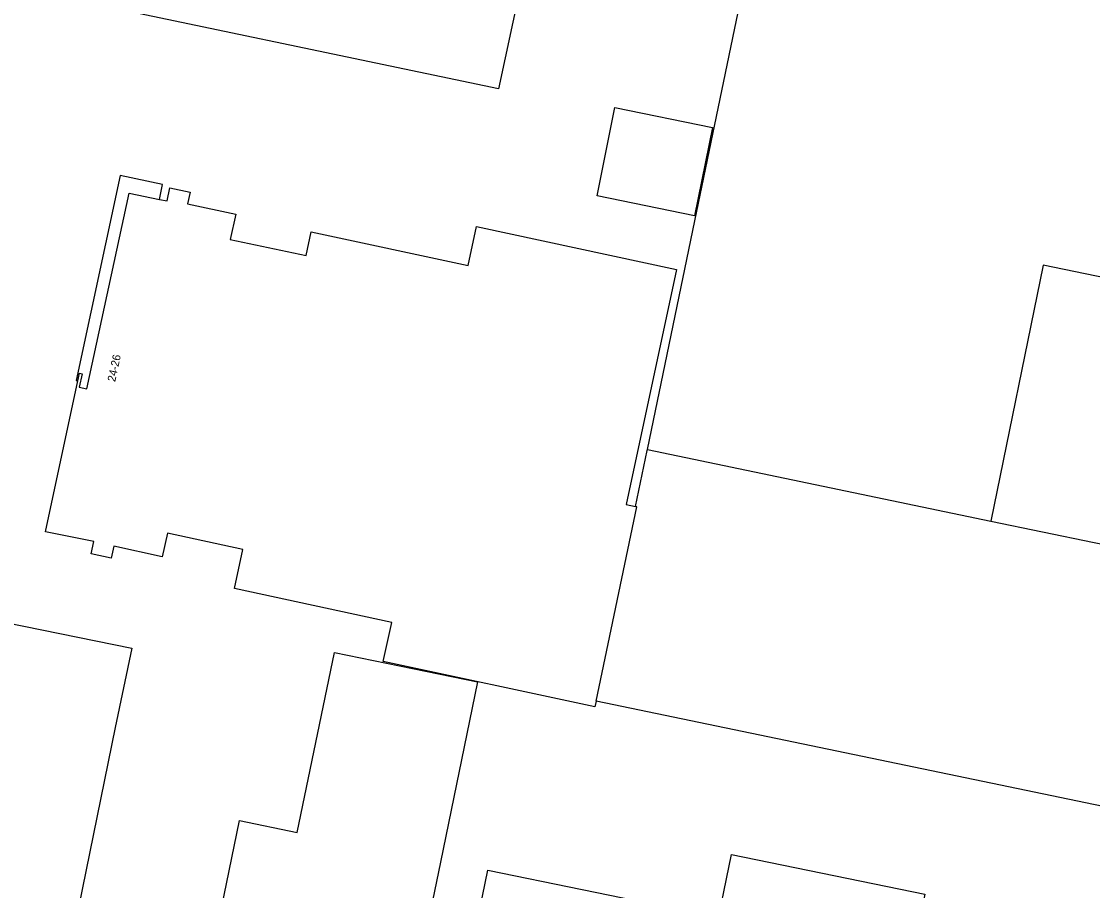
# Model space of a CAD drawing. Extents: x 157692 to 159670, y 381454 to 383289.
# Drawn here: x 158232.1 to 158365.6, y 382592.2 to 382700.6 of the extents above; entities that cross this region are included whole.
import ezdxf

# ---------------------------------------------------------------- set-up
doc = ezdxf.new("R2010")
doc.units = 0
for name, color, linetype in [('IMGEO_Pand', 7, 'Continuous'), ('IMGEO_Pand_nummerreeks', 7, 'Continuous'), ('IMGEO_Pand_overbouw', 7, 'Continuous')]:
    doc.layers.add(name, color=color, linetype=linetype)

msp = doc.modelspace()

# ---------------------------------------------------------------- linework, layer by layer
at = {"layer": 'IMGEO_Pand'}
for points in [[(158233.14, 382704.51), (158233.31, 382705.3), (158239.85, 382736.2), (158235.29, 382737.16), (158236.84, 382744.62), (158271.08, 382737.39), (158270.37, 382733.89), (158299.12, 382727.79), (158296.85, 382717.09), (158302.18, 382715.96), (158299.49, 382703.32), (158294.17, 382704.46), (158291.57, 382692.24), (158233.14, 382704.51)], [(158310.13, 382647.23), (158316.03, 382675.76), (158321.89, 382704.06), (158322.9, 382708.96), (158328.21, 382707.89), (158330.83, 382720.57), (158358, 382715), (158357.94, 382714.69), (158357.59, 382714.75), (158357.35, 382713.59), (158362.29, 382712.55), (158362.54, 382713.72), (158362.15, 382713.8), (158362.22, 382714.11), (158389.37, 382708.39), (158386.74, 382695.68), (158392.04, 382694.57), (158391.03, 382689.67), (158385.9, 382664.78), (158359.48, 382670.22), (158352.94, 382638.28)], [(158303.85, 382678.9), (158306.06, 382689.91), (158318.27, 382687.39), (158315.99, 382676.39), (158303.85, 382678.9)], [(158303.74, 382615.84), (158303.59, 382615.12), (158277.18, 382620.79), (158278.25, 382625.65), (158258.64, 382629.89), (158259.7, 382634.76), (158250.27, 382636.79), (158249.62, 382633.84), (158243.58, 382635.15), (158243.26, 382633.67), (158240.77, 382634.22), (158241.11, 382635.73), (158235.07, 382636.97), (158239.11, 382655.79), (158239.32, 382656.76), (158239.63, 382656.69), (158239.27, 382655.01), (158240.23, 382654.8), (158245.49, 382679.23), (158249.27, 382678.44), (158250.23, 382678.24), (158250.59, 382679.9), (158253.1, 382679.35), (158252.77, 382677.89), (158258.8, 382676.59), (158258.12, 382673.44), (158267.56, 382671.42), (158268.19, 382674.38), (158287.78, 382670.18), (158288.83, 382675.04), (158313.78, 382669.69), (158307.48, 382640.35), (158308.65, 382640.1)], [(158308.65, 382640.1), (158310.11, 382647.12), (158310.13, 382647.23)], [(158310.13, 382647.23), (158352.94, 382638.28)], [(158303.74, 382615.84), (158308.82, 382640.07), (158308.65, 382640.1)], [(158352.94, 382638.28), (158391.62, 382630.32), (158385.16, 382598.9), (158303.74, 382615.84)], [(158206.93, 382583.15), (158214.19, 382618.55), (158219.17, 382617.54), (158219.47, 382619.02), (158220.15, 382622.37), (158227.41, 382620.9), (158227.57, 382621.68), (158227.77, 382622.63), (158227.35, 382622.71), (158227.43, 382623.1), (158227.84, 382623.01), (158228.44, 382625.97), (158229.8, 382625.7), (158229.88, 382626.12), (158230.22, 382626.05), (158230.14, 382625.63), (158245.82, 382622.45), (158243.76, 382612.55), (158236.47, 382576.8)], [(158278.52, 382567.58), (158277.52, 382562.68), (158271.57, 382563.89), (158265.48, 382565.14), (158252.48, 382567.79), (158252.71, 382568.92), (158249.67, 382569.54), (158249.44, 382568.41), (158249.1, 382568.48), (158251.4, 382579.74), (158254.78, 382579.05), (158259.25, 382600.93), (158266.46, 382599.44), (158271.1, 382621.91), (158288.94, 382618.22), (158284.32, 382595.75), (158278.52, 382567.58)], [(158344.72, 382591.73), (158338.21, 382560.07), (158337.21, 382555.17), (158335.3, 382555.59), (158331.44, 382545.45), (158315.35, 382551.58), (158315.45, 382551.88), (158317.62, 382551.14), (158319.14, 382555.26), (158318.49, 382555.38), (158318.99, 382557.93), (158320.06, 382557.73), (158320.39, 382558.62), (158318.99, 382558.9), (158319.99, 382563.8), (158321.08, 382569.15), (158315.21, 382570.33), (158316.21, 382575.23), (158320.62, 382596.68), (158344.72, 382591.73)], [(158307.71, 382560.55), (158306.71, 382555.65), (158295.16, 382558.04), (158292.52, 382558.58), (158291.43, 382561.73), (158289.69, 382562.23), (158293.14, 382578.91), (158287.24, 382580.09), (158288.24, 382584.99), (158290.24, 382594.75), (158313.75, 382589.93), (158307.71, 382560.55)]]:
    msp.add_lwpolyline(points, dxfattribs=at)
at = {"layer": 'IMGEO_Pand_overbouw'}
msp.add_lwpolyline([(158249.27, 382678.44), (158249.66, 382680.3), (158244.38, 382681.44), (158238.88, 382655.83), (158239.11, 382655.79), (158239.32, 382656.76), (158239.63, 382656.69), (158239.27, 382655.01), (158240.23, 382654.8), (158245.49, 382679.23)], close=True, dxfattribs=at)

# ---------------------------------------------------------------- texts
at = {"layer": 'IMGEO_Pand_nummerreeks'}
msp.add_text('24-26', height=1, rotation=77.8383, dxfattribs=at).set_placement((158243.76, 382655.62))

doc.saveas('drawing.dxf')
